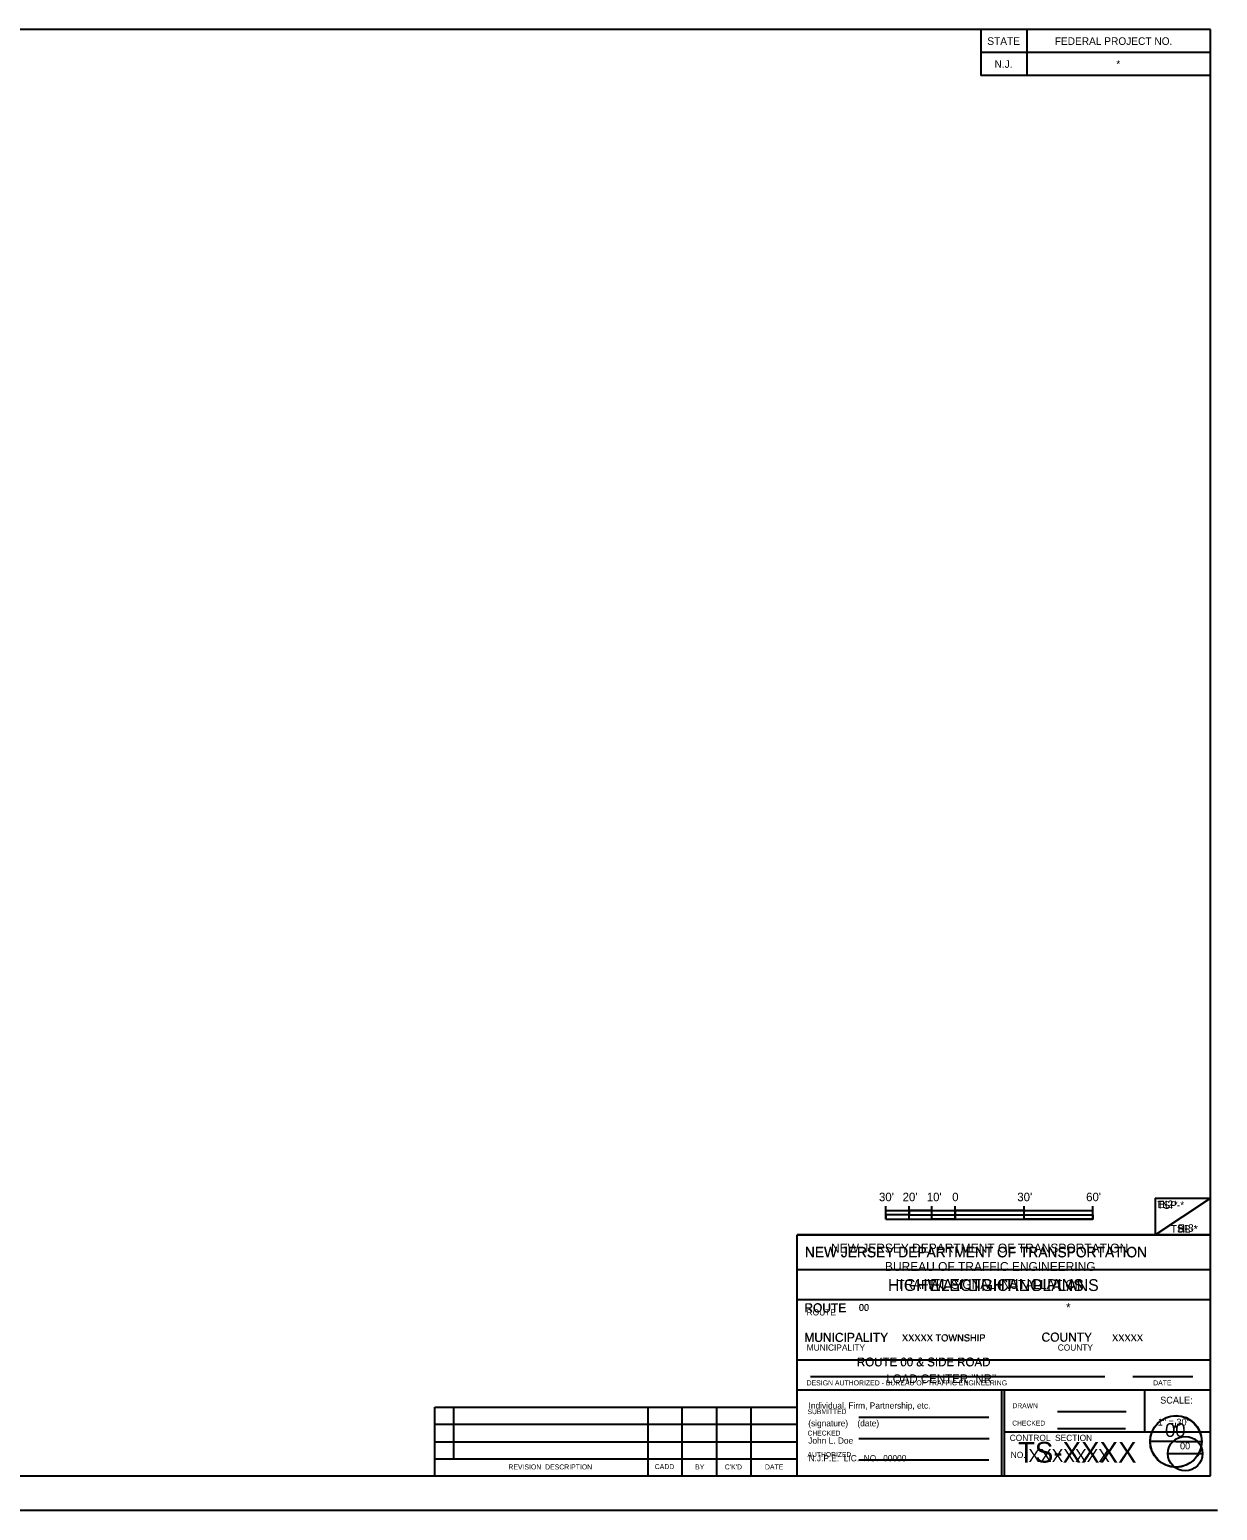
# Model space of a CAD drawing. Extents: x 488740 to 507913, y 466518 to 497949.
# Drawn here: x 507909.198 to 507910.636, y 496044.573 to 496046.365 of the extents above; entities that cross this region are included whole.
import ezdxf

# ---------------------------------------------------------------- set-up
doc = ezdxf.new("R2010")
doc.units = 0
for name, color, linetype in [('1', 7, 'Continuous'), ('11', 7, 'Continuous'), ('25', 7, 'Continuous'), ('26', 7, 'Continuous'), ('27', 7, 'Continuous'), ('38', 7, 'Continuous'), ('9', 7, 'Continuous')]:
    doc.layers.add(name, color=color, linetype=linetype)

msp = doc.modelspace()

# ---------------------------------------------------------------- linework, layer by layer
at = {"layer": '1'}
for p, q in [((507910.6273, 496046.3645), (507907.8773, 496046.3645)), ((507910.3495, 496046.3645), (507910.3495, 496046.3089)), ((507910.4051, 496046.3645), (507910.4051, 496046.3089)), ((507910.6273, 496044.6145), (507910.6273, 496046.3645)), ((507910.4051, 496046.3367), (507910.3495, 496046.3367)), ((507910.6273, 496046.3367), (507910.4051, 496046.3367)), ((507910.6273, 496046.3089), (507910.3495, 496046.3089)), ((507910.6273, 496044.6145), (507910.6273, 496044.9731)), ((507910.2345, 496044.9253), (507910.2345, 496044.941)), ((507910.2628, 496044.9253), (507910.2628, 496044.941)), ((507910.2903, 496044.9253), (507910.2903, 496044.941)), ((507910.3185, 496044.9253), (507910.3185, 496044.941)), ((507910.4019, 496044.9253), (507910.4019, 496044.941)), ((507910.4852, 496044.9253), (507910.4852, 496044.941)), ((507910.2345, 496044.9358), (507910.4852, 496044.9358)), ((507910.2345, 496044.9253), (507910.4852, 496044.9253)), ((507907.8773, 496044.6145), (507910.6273, 496044.6145)), ((507907.8773, 496044.6145), (507910.6273, 496044.6145)), ((507910.6358, 496044.5728), (507907.7241, 496044.5728)), ((507910.6358, 496044.5728), (507907.7241, 496044.5728))]:
    msp.add_line(p, q, dxfattribs=at)
for points in [[(507910.2345, 496044.9302), (507910.2352, 496044.9305)], [(507910.2628, 496044.9253), (507910.2628, 496044.9253)]]:
    msp.add_lwpolyline(points, dxfattribs=at)
for points in [[(507910.2345, 496044.9253), (507910.2628, 496044.9253), (507910.2628, 496044.9305), (507910.2345, 496044.9305)], [(507910.2628, 496044.9305), (507910.2903, 496044.9305), (507910.2903, 496044.9358), (507910.2628, 496044.9358)], [(507910.2903, 496044.9305), (507910.3185, 496044.9305), (507910.3185, 496044.9253), (507910.2903, 496044.9253)], [(507910.3185, 496044.9305), (507910.4019, 496044.9305), (507910.4019, 496044.9358), (507910.3185, 496044.9358)], [(507910.4019, 496044.9305), (507910.4852, 496044.9305), (507910.4852, 496044.9253), (507910.4019, 496044.9253)]]:
    msp.add_lwpolyline(points, close=True, dxfattribs=at)
at = {"layer": '25'}
for p, q in [((507910.5607, 496044.9062), (507910.6273, 496044.9505)), ((507910.5607, 496044.9505), (507910.6273, 496044.9505)), ((507910.5607, 496044.9505), (507910.5607, 496044.9062)), ((507910.1273, 496044.6145), (507910.1273, 496044.9062)), ((507910.6273, 496044.9062), (507910.1273, 496044.9062)), ((507910.1273, 496044.8642), (507910.6273, 496044.8642)), ((507910.6273, 496044.7182), (507910.1273, 496044.7182)), ((507910.3747, 496044.7182), (507910.3747, 496044.6145)), ((507910.5856, 496044.6562), (507910.5548, 496044.6562)), ((507910.5856, 496044.6562), (507910.6168, 496044.6562))]:
    msp.add_line(p, q, dxfattribs=at)
msp.add_circle((507910.5858, 496044.6563), 0.0312, dxfattribs=at)
at = {"layer": '26'}
for p, q in [((507910.5607, 496044.9505), (507910.6273, 496044.9505)), ((507910.5607, 496044.9505), (507910.5607, 496044.9062)), ((507910.5607, 496044.9062), (507910.6273, 496044.9505)), ((507910.1273, 496044.6145), (507910.1273, 496044.9062)), ((507910.6273, 496044.9062), (507910.1273, 496044.9062)), ((507910.1273, 496044.8642), (507910.6273, 496044.8642)), ((507910.5856, 496044.6562), (507910.5548, 496044.6562)), ((507910.5856, 496044.6562), (507910.6168, 496044.6562))]:
    msp.add_line(p, q, dxfattribs=at)
msp.add_circle((507910.5856, 496044.6561), 0.0312, dxfattribs=at)
at = {"layer": '27'}
for p, q in [((507910.5607, 496044.9505), (507910.6273, 496044.9505)), ((507910.5607, 496044.9505), (507910.5607, 496044.9062)), ((507910.5607, 496044.9062), (507910.6273, 496044.9505)), ((507910.6271, 496044.906), (507910.1271, 496044.906)), ((507910.1273, 496044.6145), (507910.1273, 496044.9062)), ((507910.6271, 496044.8276), (507910.1271, 496044.8276)), ((507910.6271, 496044.7545), (507910.1271, 496044.7545)), ((507910.1434, 496044.7349), (507910.4997, 496044.7349)), ((507910.5335, 496044.7349), (507910.606, 496044.7349)), ((507910.6271, 496044.7181), (507910.1271, 496044.7181)), ((507910.378, 496044.6145), (507910.378, 496044.7182)), ((507910.5482, 496044.6677), (507910.5482, 496044.7182)), ((507909.6886, 496044.6978), (507910.1273, 496044.6978)), ((507909.6886, 496044.6145), (507909.6886, 496044.6978)), ((507909.7118, 496044.6352), (507909.7118, 496044.6978)), ((507909.9471, 496044.6145), (507909.9471, 496044.6978)), ((507909.9882, 496044.6145), (507909.9882, 496044.6978)), ((507910.0299, 496044.6145), (507910.0299, 496044.6978)), ((507910.0715, 496044.6145), (507910.0715, 496044.6978)), ((507910.2021, 496044.6857), (507910.3593, 496044.6857)), ((507910.2021, 496044.6857), (507910.3593, 496044.6857)), ((507910.4425, 496044.6924), (507910.5256, 496044.6924)), ((507909.6886, 496044.6772), (507910.1273, 496044.6772)), ((507910.6271, 496044.6675), (507910.3778, 496044.6675)), ((507910.4425, 496044.6718), (507910.5246, 496044.6718)), ((507909.6886, 496044.6558), (507910.1273, 496044.6558)), ((507910.2021, 496044.6598), (507910.3596, 496044.6598)), ((507910.2021, 496044.6598), (507910.3596, 496044.6598)), ((507909.6886, 496044.6352), (507910.1273, 496044.6352)), ((507910.2021, 496044.6339), (507910.3593, 496044.6339)), ((507910.576, 496044.6417), (507910.6178, 496044.6417))]:
    msp.add_line(p, q, dxfattribs=at)
msp.add_circle((507910.5969, 496044.6415), 0.0209, dxfattribs=at)

# ---------------------------------------------------------------- texts
at = {"layer": '1'}
for s, height, p in [('STATE', 0.00917, (507910.3574, 496046.346)), ('FEDERAL PROJECT NO.', 0.009166, (507910.439, 496046.346)), ('N.J.', 0.00917, (507910.3661, 496046.3183)), ('*', 0.00917, (507910.5135, 496046.3183)), ("30'", 0.01032, (507910.2263, 496044.9469)), ("20'", 0.01032, (507910.2549, 496044.9469)), ("10'", 0.01032, (507910.2841, 496044.9469)), ('0', 0.0103, (507910.3149, 496044.9469)), ("30'", 0.01032, (507910.3937, 496044.9469)), ("60'", 0.01032, (507910.477, 496044.9469))]:
    msp.add_text(s, height=height, dxfattribs=at).set_placement(p)
at = {"layer": '11'}
for s, height, p in [('HL-*', 0.00917, (507910.5633, 496044.9386)), ('HL-*', 0.00917, (507910.5875, 496044.909)), ('HIGHWAY LIGHTING PLANS', 0.014299, (507910.2372, 496044.8383))]:
    msp.add_text(s, height=height, dxfattribs=at).set_placement(p)
at = {"layer": '25'}
for s, height, p in [('NEW JERSEY DEPARTMENT OF TRANSPORTATION', 0.012467, (507910.1368, 496044.8793)), ('ROUTE', 0.01083, (507910.1362, 496044.8127)), ('00                      ', 0.008299, (507910.2021, 496044.8143)), ('*', 0.0108, (507910.4526, 496044.813)), ('MUNICIPALITY', 0.010827, (507910.1362, 496044.7769)), ('XXXXX TOWNSHIP    ', 0.0084, (507910.2543, 496044.7776)), ('COUNTY', 0.01083, (507910.4232, 496044.7772)), ('XXXXX        ', 0.0084, (507910.5085, 496044.7776)), ('             ROUTE 00 & SIDE ROAD            ', 0.0104, (507910.1496, 496044.7474)), ('*', 0.0167, (507910.5807, 496044.6621)), ('CONTROL  SECTION', 0.007545, (507910.3845, 496044.6568)), ('NO.', 0.00755, (507910.3858, 496044.6362)), ('XXXXXXX  ', 0.0158, (507910.4071, 496044.6312))]:
    msp.add_text(s, height=height, dxfattribs=at).set_placement(p)
at = {"layer": '26'}
for s, height, p in [('NEW JERSEY DEPARTMENT OF TRANSPORTATION', 0.012467, (507910.1365, 496044.8789)), ('ROUTE', 0.01083, (507910.1358, 496044.8123)), ('00                      ', 0.008299, (507910.2018, 496044.814)), ('*', 0.0108, (507910.4526, 496044.813)), ('MUNICIPALITY', 0.010827, (507910.1358, 496044.7766)), ('XXXXX TOWNSHIP    ', 0.0084, (507910.2539, 496044.7772)), ('COUNTY', 0.01083, (507910.4229, 496044.7769)), ('XXXXX        ', 0.0084, (507910.5082, 496044.7772)), ('             ROUTE 00 & SIDE ROAD            ', 0.0104, (507910.1493, 496044.747)), ('               LOAD CENTER "NR"              ', 0.0104, (507910.1773, 496044.727)), ('Individual, Firm, Partnership, etc.', 0.007545, (507910.1411, 496044.6959)), ('(signature)    (date)', 0.007545, (507910.1407, 496044.6745)), ('00', 0.01667, (507910.5725, 496044.6617)), ('John L. Doe', 0.007545, (507910.1407, 496044.6535)), ('N.J.P.E.  LIC.  NO.  00000', 0.007545, (507910.1411, 496044.6322))]:
    msp.add_text(s, height=height, dxfattribs=at).set_placement(p)
at = {"layer": '27'}
for s, height, p in [('NEW JERSEY DEPARTMENT OF TRANSPORTATION', 0.010827, (507910.1683, 496044.8848)), ('BUREAU OF TRAFFIC ENGINEERING', 0.010827, (507910.2335, 496044.8625)), ('TRAFFIC SIGNAL INSTALLATION', 0.010827, (507910.2484, 496044.8409)), ('ROUTE', 0.00755, (507910.1388, 496044.8087)), ('MUNICIPALITY', 0.007545, (507910.1388, 496044.7661)), ('COUNTY', 0.00755, (507910.4426, 496044.7661)), ('DESIGN AUTHORIZED - BUREAU OF TRAFFIC ENGINEERING             ', 0.006035, (507910.1387, 496044.7241)), ('DATE', 0.00604, (507910.5581, 496044.7241)), ('SCALE:', 0.00827, (507910.5666, 496044.7021)), ('SUBMITTED                           ', 0.005906, (507910.1398, 496044.6893)), ('DRAWN', 0.00591, (507910.3878, 496044.6965)), ('CHECKED                            ', 0.005906, (507910.1398, 496044.6634)), ('CHECKED', 0.00591, (507910.3875, 496044.6755)), ('1" = 30\'', 0.00827, (507910.5636, 496044.6755)), ('TS-XXXX', 0.0251, (507910.3944, 496044.6306)), ('00', 0.00827, (507910.5906, 496044.6467)), ('AUTHORIZED                          ', 0.005906, (507910.1398, 496044.6375)), ('REVISION  DESCRIPTION', 0.006035, (507909.7778, 496044.6224)), ('CADD', 0.00604, (507909.9549, 496044.6228)), ('BY', 0.00604, (507910.0039, 496044.6224)), ("C'K'D", 0.00604, (507910.0397, 496044.6224)), ('DATE', 0.00604, (507910.0883, 496044.6224))]:
    msp.add_text(s, height=height, dxfattribs=at).set_placement(p)
at = {"layer": '38'}
for p in [(507910.5629, 496044.9377), (507910.5794, 496044.9088)]:
    msp.add_text('TSP-*', height=0.00917, dxfattribs=at).set_placement(p)
at = {"layer": '9'}
for s, height, p in [('E-2', 0.00917, (507910.5633, 496044.9386)), ('E-3', 0.00917, (507910.5881, 496044.9099)), ('ELECTRICAL PLANS', 0.014299, (507910.2881, 496044.8383))]:
    msp.add_text(s, height=height, dxfattribs=at).set_placement(p)

doc.saveas('drawing.dxf')
